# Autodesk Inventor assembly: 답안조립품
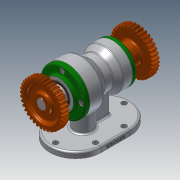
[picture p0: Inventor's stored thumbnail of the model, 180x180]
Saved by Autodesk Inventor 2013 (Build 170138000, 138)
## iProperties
Created: 2020-01
Part Number: 답안조립품
Document SubType Name: Assembly
Designer: user
Author: user
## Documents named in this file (13)
- C:\Users\user\Desktop\700104V1014\답안조립품.iam
- C:\Users\user\Desktop\700104V1014\본체.ipt
- C:\Users\user\Desktop\700104V1014\Ű 5 x 5 x 18.ipt
- C:\Users\user\Desktop\700104V1014\뒤커버.ipt
- C:\Users\user\Desktop\700104V1014\멈춤나사 M3.ipt
- C:\Users\user\Desktop\700104V1014\베어링 6203.ipt
- C:\Users\user\Desktop\700104V1014\베어링 6205.ipt
- C:\Users\user\Desktop\700104V1014\볼트 M4.ipt
- C:\Users\user\Desktop\700104V1014\스퍼기어.ipt
- C:\Users\user\Desktop\700104V1014\앞커버.ipt
- C:\Users\user\Desktop\700104V1014\오일 실 17 30 8.ipt
- C:\Users\user\Desktop\700104V1014\오일 실 25 38 8.ipt
- C:\Users\user\Desktop\700104V1014\축.ipt
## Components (2 placed, 1 different names)
1. Ű 5 x 5 x 18:1
2. Ű 5 x 5 x 18:2
